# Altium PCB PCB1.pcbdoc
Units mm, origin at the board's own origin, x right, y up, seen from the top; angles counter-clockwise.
Board outline 47.75 x 46.1 mm, 2 copper layers (Top Layer, Bottom Layer); 17 components, 14 nets, 43 pads, 36 vias.
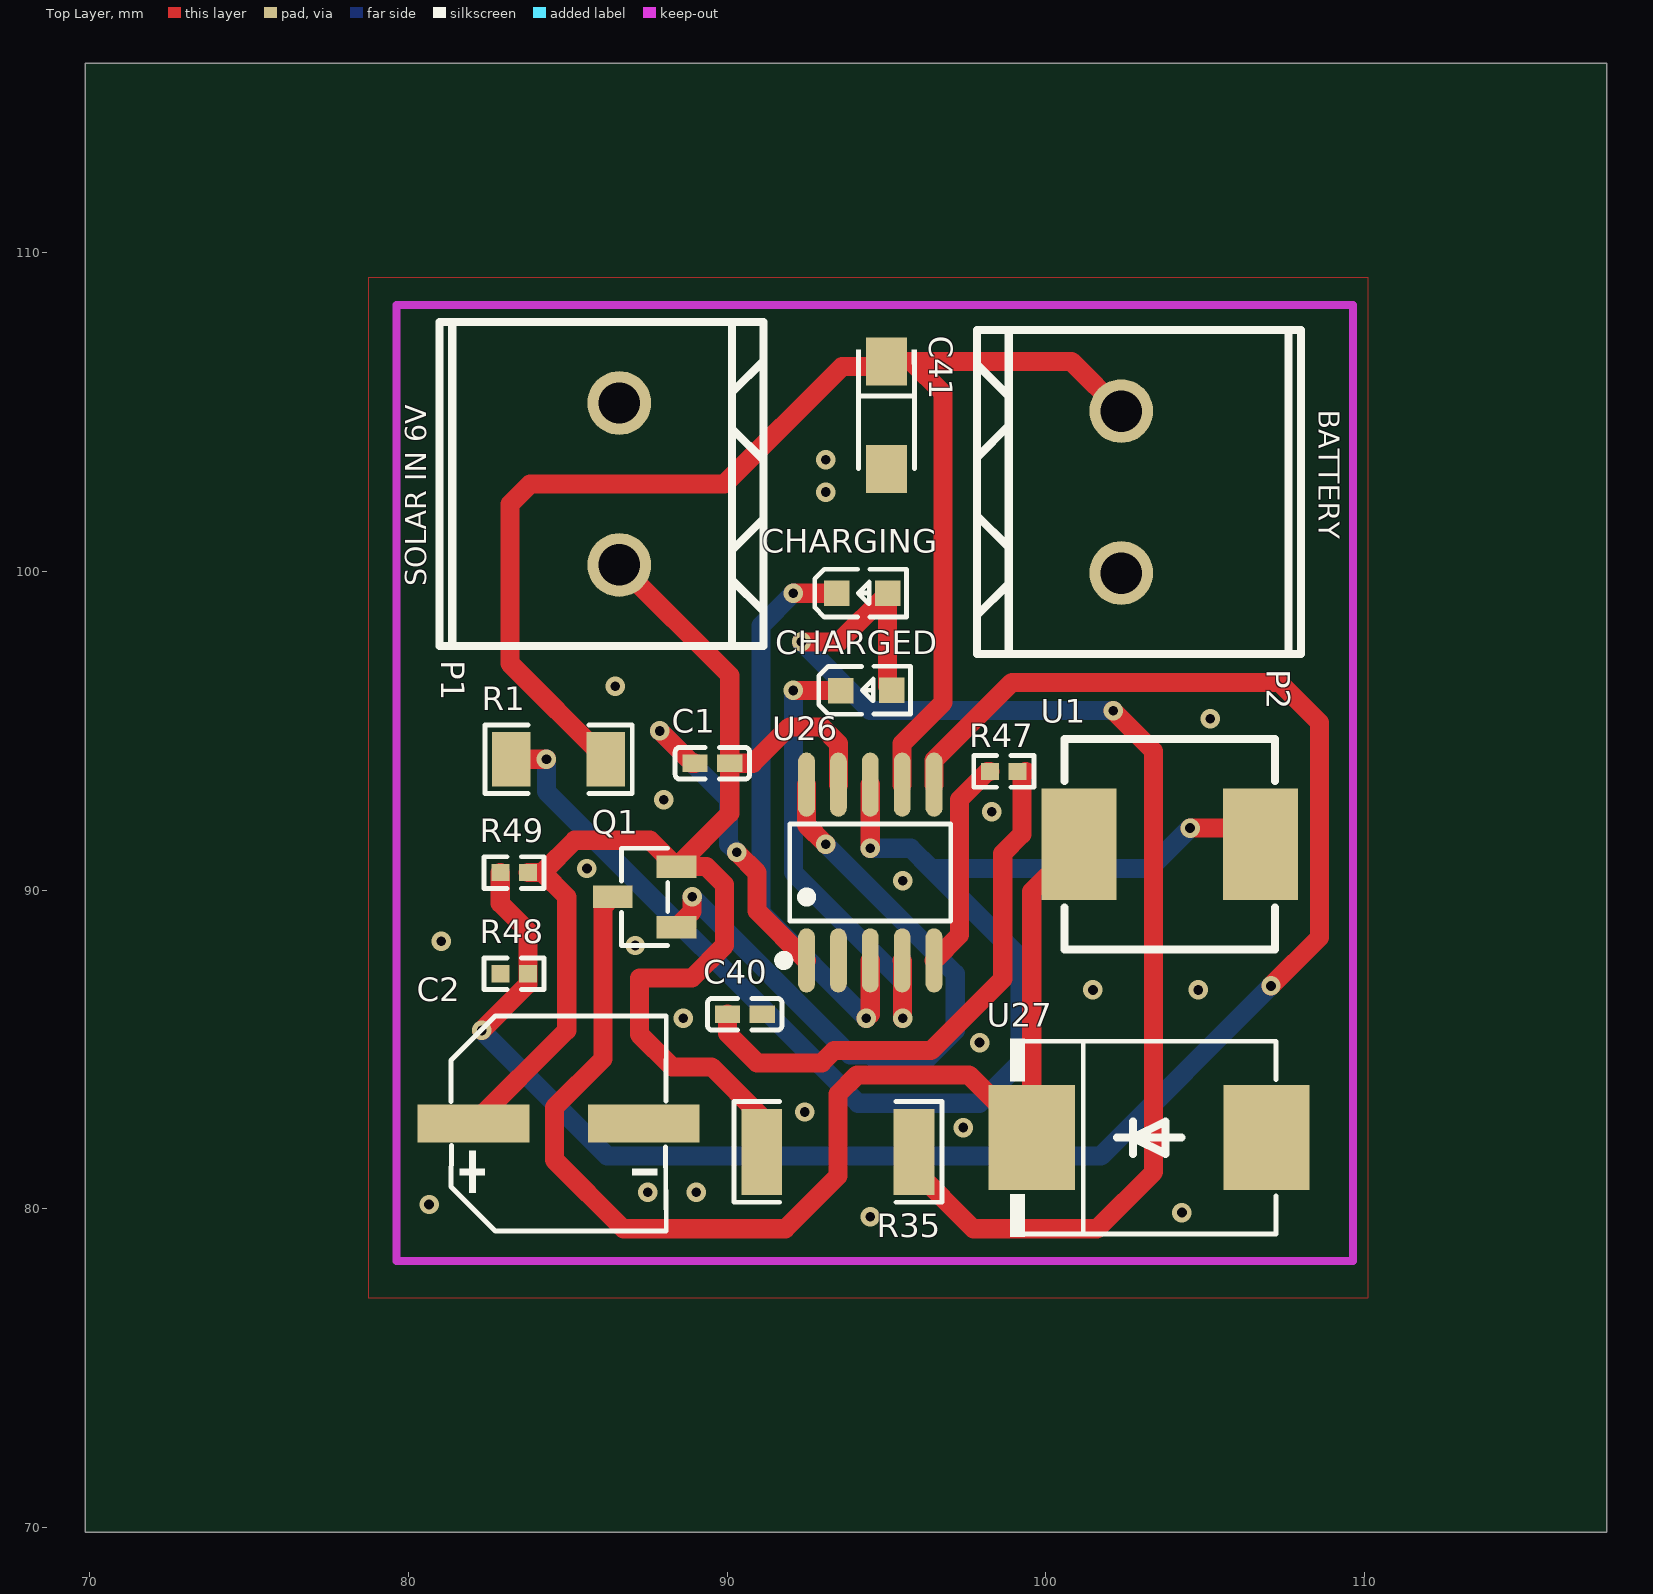
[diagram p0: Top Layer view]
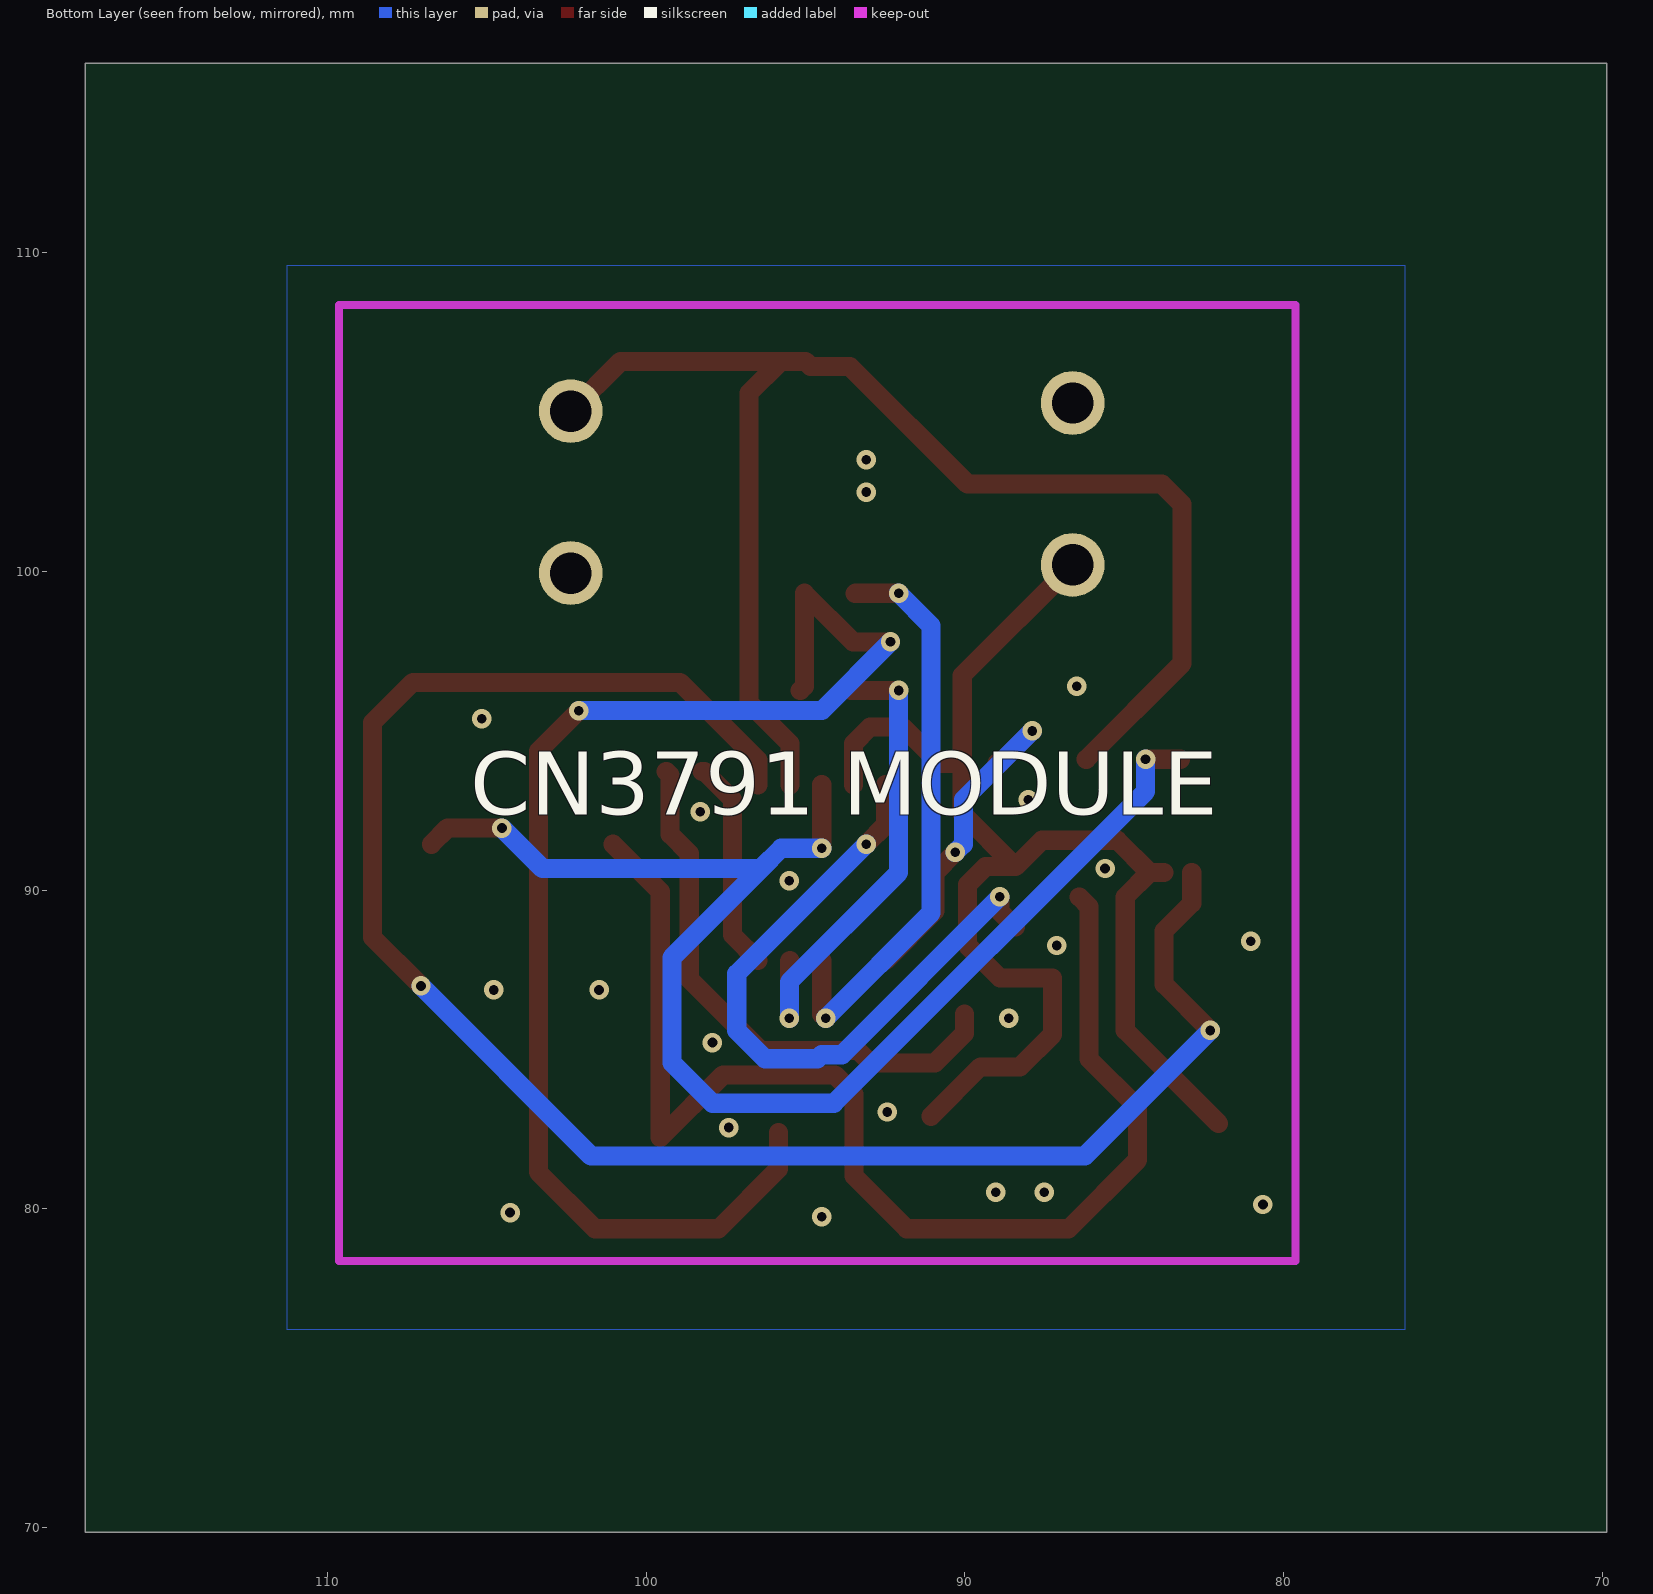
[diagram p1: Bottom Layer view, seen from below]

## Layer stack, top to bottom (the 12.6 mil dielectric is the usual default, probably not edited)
Top Layer: signal copper (thickness not stored)
Dielectric: dielectric 0.32, FR-4, Dk 4.8
Bottom Layer: signal copper (thickness not stored)

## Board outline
117.602,69.85 69.85,69.85 69.85,115.951 117.602,115.951

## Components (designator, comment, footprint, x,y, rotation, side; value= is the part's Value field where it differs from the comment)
C1 "CT41G-0402-2X1-16V-0.1μF-K(N)" C0402 89.535,93.98 r0 top
C2 "RVT47UF50V67RV0029" CAP-SMD_BD6.3-L6.6-W6.6-LS7.6-FD 84.709,82.677 r0 top
C40 "0402B224K160NT" C0402 90.551,86.106 r0 top
C41 "CA45-A-16V-10uF-K" CAP-SMD_L3.2-W1.6-RD 94.996,104.902 r270 top
CHARGED "XL-1608UGC-04" LED0603-RD_GREEN 94.361,96.266 r0 top
CHARGING "19-217/R6C-AL1M2VY/3T" LED0603-RD 94.234,99.314 r0 top
P1 "WJ500V-5.08-2P" CONN-TH_2P-P5.00_WJ500V-5.08-2P 86.614,102.743 r90 top
P2 "WJ500V-5.08-2P" CONN-TH_2P-P5.00_WJ500V-5.08-2P 102.362,102.489 r270 top
Q1 "SI2305_C2909911" SOT-23-3_L2.9-W1.3-P1.90-LS2.4-BR 87.408,89.789 r0 top
R1 "FRL1206JR050TS" R1206 84.709,94.107 r0 top
R35 "201007J0222T4E" R2010 93.472,81.788 r180 top
R47 "RC0402FR-07120RL" R0402 98.679,93.726 r180 top
R48 "RC0402FR-0756KL" R0402 83.312,87.376 r0 top
R49 "RM04FTN1783" R0402 83.312,90.551 r0 top
U1 "CYA0630-10UH" IND-SMD_L7.2-W6.6_GPSR07X0 103.886,91.44 r0 top
U26 "CN3791" SSOP-10_L4.9-W3.9-P1.00-LS6.0-BL 94.488,90.551 r0 top
U27 "SS54_C5307984" SMC_L6.9-W5.9-LS7.9-RD 103.24,82.234 r0 top

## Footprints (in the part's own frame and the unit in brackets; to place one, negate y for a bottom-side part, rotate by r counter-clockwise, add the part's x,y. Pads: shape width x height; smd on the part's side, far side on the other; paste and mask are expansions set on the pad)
C0402 [mm]
  rect 0.79x0.54 smd: 1(-0.545,0) 2(0.545,0)
  silkscreen extent -1.17,-0.5 1.17,0.5
CAP-SMD_BD6.3-L6.6-W6.6-LS7.6-FD [mm]
  rect 3.5x1.2 smd: 1(-2.67,0) 2(2.67,0)
  silkscreen extent -3.38,-3.38 3.38,3.38
CAP-SMD_L3.2-W1.6-RD [mm]
  rect 1.5x1.296 smd: 1(-1.686,0) 2(1.686,0)
  silkscreen extent -2.06,-0.95 1.68,0.95
CONN-TH_2P-P5.00_WJ500V-5.08-2P [mm]
  round 2 hole 1.3: 1(-2.54,0) 2(2.54,0)
  silkscreen extent -5.08,-4.52 5.08,5.64
IND-SMD_L7.2-W6.6_GPSR07X0 [mm]
  rect 2.35x3.5 smd: 1(-2.85,0) 2(2.85,0)
  silkscreen extent -3.3,-3.3 3.3,3.3
LED0603-RD [mm]
  rect 0.8x0.8 smd: 1(-0.799,-0.003) 2(0.799,0.003)
  silkscreen extent -1.49,-0.75 1.39,0.76
LED0603-RD_GREEN [mm]
  rect 0.8x0.8 smd: 1(-0.799,-0.003) 2(0.799,0.003)
  silkscreen extent -1.49,-0.75 1.39,0.76
R0402 [mm]
  rect 0.566x0.54 smd: 1(-0.433,0) 2(0.433,0)
  silkscreen extent -0.94,-0.5 0.94,0.5
R1206 [mm]
  rect 1.208x1.701 smd: 1(-1.479,0) 2(1.479,0)
  silkscreen extent -2.31,-1.08 2.31,1.08
R2010 [mm]
  rect 1.283x2.7 smd: 1(-2.391,0) 2(2.391,0)
  silkscreen extent -3.26,-1.58 3.26,1.58
SMC_L6.9-W5.9-LS7.9-RD [mm]
  rect 2.7x3.3 smd: 1(-3.686,0) 2(3.686,0)
  silkscreen extent -4.36,-3.1 3.98,3.1
SOT-23-3_L2.9-W1.3-P1.90-LS2.4-BR [mm]
  rect 1.25x0.7 smd: 1(1,-0.95) 2(1,0.95) 3(-1,0)
  silkscreen extent -0.73,-1.53 0.73,1.53
SSOP-10_L4.9-W3.9-P1.00-LS6.0-BL [mm]
  oval 0.525x2.014 smd: 1(-2,-2.757) 2(-1,-2.757) 3(0,-2.757) 4(1,-2.757) 5(2,-2.757) 6(2,2.757) 7(1,2.757) 8(0,2.757) 9(-1,2.757) 10(-2,2.757)
  silkscreen extent -2.86,-2.91 2.53,1.52

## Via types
v1: diameter 0.61, hole 0.305, Top Layer to Bottom Layer, 36 vias

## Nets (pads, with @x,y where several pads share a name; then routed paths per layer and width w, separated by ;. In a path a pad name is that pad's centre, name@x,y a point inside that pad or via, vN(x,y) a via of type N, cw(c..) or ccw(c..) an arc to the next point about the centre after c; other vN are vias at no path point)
$1N447: CHARGED.1 U26.4 | length 15
  Top Layer w0.6: v1(92.075,96.266) 93.558,96.266 CHARGED.1 ; U26.4 95.504,87.778 v1(95.504,85.979)
  Bottom Layer w0.6: v1(92.075,96.266) 92.075,90.551 95.504,87.122 v1(95.504,85.979)
$1N450: CHARGING.1 U26.3 | length 18.4
  Top Layer w0.6: v1(92.075,99.314) 93.431,99.314 CHARGING.1 ; v1(94.361,85.979) 94.488,86.106 U26.3
  Bottom Layer w0.6: v1(92.075,99.314) 91.059,98.298 91.059,89.281 v1(94.361,85.979)
$1N458: CHARGED.2 CHARGING.2 R35.1 | length 42.3
  Top Layer w0.6: v1(92.329,97.79) 93.506,97.79 CHARGING.2 95.033,96.396 CHARGED.2 ; R35.1@95.842,82.396 95.842,81.254 97.722,79.375 101.6,79.375 103.378,81.153 103.378,94.361 v1(102.108,95.631)
  Bottom Layer w0.6: v1(92.329,97.79) 94.488,95.631 v1(102.108,95.631)
$1N745: C40.1 R47.1 | length 17.5
  Top Layer w0.6: C40.1 90.006,85.508 90.932,84.582 92.964,84.582 93.345,84.963 96.393,84.963 98.644,87.214 98.644,91.151 99.244,91.751 99.244,93.604 R47.1@99.366,93.726
$1N751: R47.2 U26.5 | length 6.7
  Top Layer w0.6: U26.5 97.282,88.588 97.282,92.837 98.171,93.726 R47.2
$1N753: Q1.3 U1.1 U27.1 | length 39
  Top Layer w0.6: Q1.3 86.106,89.487 86.106,84.709 84.582,83.185 84.582,81.534 86.741,79.375 91.821,79.375 93.472,81.026 93.472,83.601 94.072,84.201 97.587,84.201 U27.1 99.554,89.958 U1.1
$1N867: C1.1 U26.1 | length 10.6
  Top Layer w0.6: v1(87.884,94.996) 88.9,93.98 C1.1 ; v1(90.297,91.186) 90.932,90.551 90.932,89.35 U26.1
  Bottom Layer w0.6: v1(87.884,94.996) 90.043,92.837 90.043,91.44 v1(90.297,91.186)
$1N1034: R48.2 R49.1 U26.6 | length 57.8
  Top Layer w0.6: v1(82.296,85.598) 83.745,87.047 R48.2 83.745,88.721 82.879,89.587 R49.1 ; U26.6 96.488,94.075 98.933,96.52 107.315,96.52 108.585,95.25 108.585,88.519 v1(107.061,86.995)
  Bottom Layer w0.6: v1(82.296,85.598) 86.233,81.661 101.727,81.661 v1(107.061,86.995)
$1N1115: R1.1 U1.2 U26.8 | length 44
  Top Layer w0.6: R1.1 v1(84.328,94.107) ; v1(94.488,91.313) U26.8 ; v1(104.521,91.948) 106.228,91.948 U1.2
  Bottom Layer w0.6: v1(84.328,94.107) 84.328,93.091 94.107,83.312 97.917,83.312 99.187,84.582 99.187,87.884 96.393,90.678 ; v1(94.488,91.313) 95.758,91.313 96.393,90.678 ; v1(104.521,91.948) 103.251,90.678 96.393,90.678
$1N1346: Q1.1 U26.10 | length 21.5
  Top Layer w0.6: Q1.1 88.9,89.331 v1(88.9,89.789) ; U26.10 92.488,92.043 v1(93.091,91.44)
  Bottom Layer w0.6: v1(88.9,89.789) 93.853,84.836 94.488,84.836 94.615,84.709 96.266,84.709 97.155,85.598 97.155,87.376 v1(93.091,91.44)
GND: C2.2 C40.2 C41.2 P1.2 P2.2 R48.1 U26.2 U27.2
  other v1: 94.488,79.756 104.267,79.883 80.645,80.137 87.503,80.518 89.027,80.518 97.409,82.55 92.436,83.038 97.917,85.217 88.621,85.977 101.473,86.868 104.775,86.868 87.11,88.262 81.026,88.392 95.504,90.297 85.598,90.678 98.298,92.456 88.011,92.837 105.156,95.377 86.487,96.393 93.091,102.489 93.091,103.505
INPUT: C1.2 C2.1 P1.1 Q1.2 R35.2 R49.2 U26.9 | length 45.2
  Top Layer w0.6: C2.1 84.963,85.601 84.963,89.789 84.201,90.551 ; R49.2 84.201,90.551 ; P1.1 90.08,96.737 C1.2 ; R35.2@91.06,82.904 89.509,84.455 88.265,84.455 87.249,85.471 87.249,87.249 88.9,87.249 89.916,88.265 89.916,90.17 89.347,90.739 Q1.2 ; U26.9 93.488,94.599 92.964,95.123 91.948,95.123 90.805,93.98 C1.2 ; 84.201,90.551 85.217,91.567 87.579,91.567 Q1.2 ; Q1.2 90.08,92.411 C1.2
OUTPUT: C41.1 P2.1 R1.2 U26.7 | length 45.2
  Top Layer w0.6: R1.2 83.185,97.11 83.185,102.108 83.82,102.743 89.916,102.743 93.599,106.426 94.834,106.426 C41.1 95.775,106.588 ; U26.7 95.488,94.599 96.774,95.885 96.774,105.59 95.775,106.588 ; P2.1 100.803,106.588 95.775,106.588
"": 

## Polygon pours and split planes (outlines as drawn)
GND on Top Layer (solid, remove dead copper, pour order 0): 78.74,77.216 110.109,77.216 110.109,109.22 78.74,109.22
GND on Bottom Layer (solid, remove dead copper, pour order 4): 76.2,76.2 111.252,76.2 111.252,109.601 76.2,109.601

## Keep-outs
Board Outline Layer:
  lines w0.254 net "": 79.629,78.359 109.629,78.359 109.629,108.359 79.629,108.359 79.629,78.359

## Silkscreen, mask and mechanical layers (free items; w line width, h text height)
Top Silkscreen Layer:
  text "BATTERY" at 108.553,105.071 h0.65 r270
  text "SOLAR IN 6V" at 80.55,99.539 h0.65 r90
Bottom Silkscreen Layer:
  text "CN3791 MODULE" at 105.515,92.371 h1.98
